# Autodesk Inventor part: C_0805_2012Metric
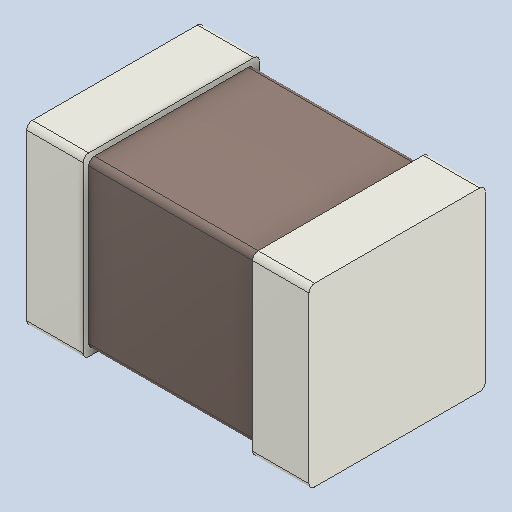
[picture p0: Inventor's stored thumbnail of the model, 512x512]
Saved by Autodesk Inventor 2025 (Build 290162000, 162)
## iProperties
Created: 2026-09
Part Number: C_0805_2012Metric
Material: Generic
Document SubType Name: Modeling
Designer: Leonardo
Density: 1 g/cm^3
Appearance: Default
Author: Leonardo
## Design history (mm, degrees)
feature "Base1"
body "Solid1"
